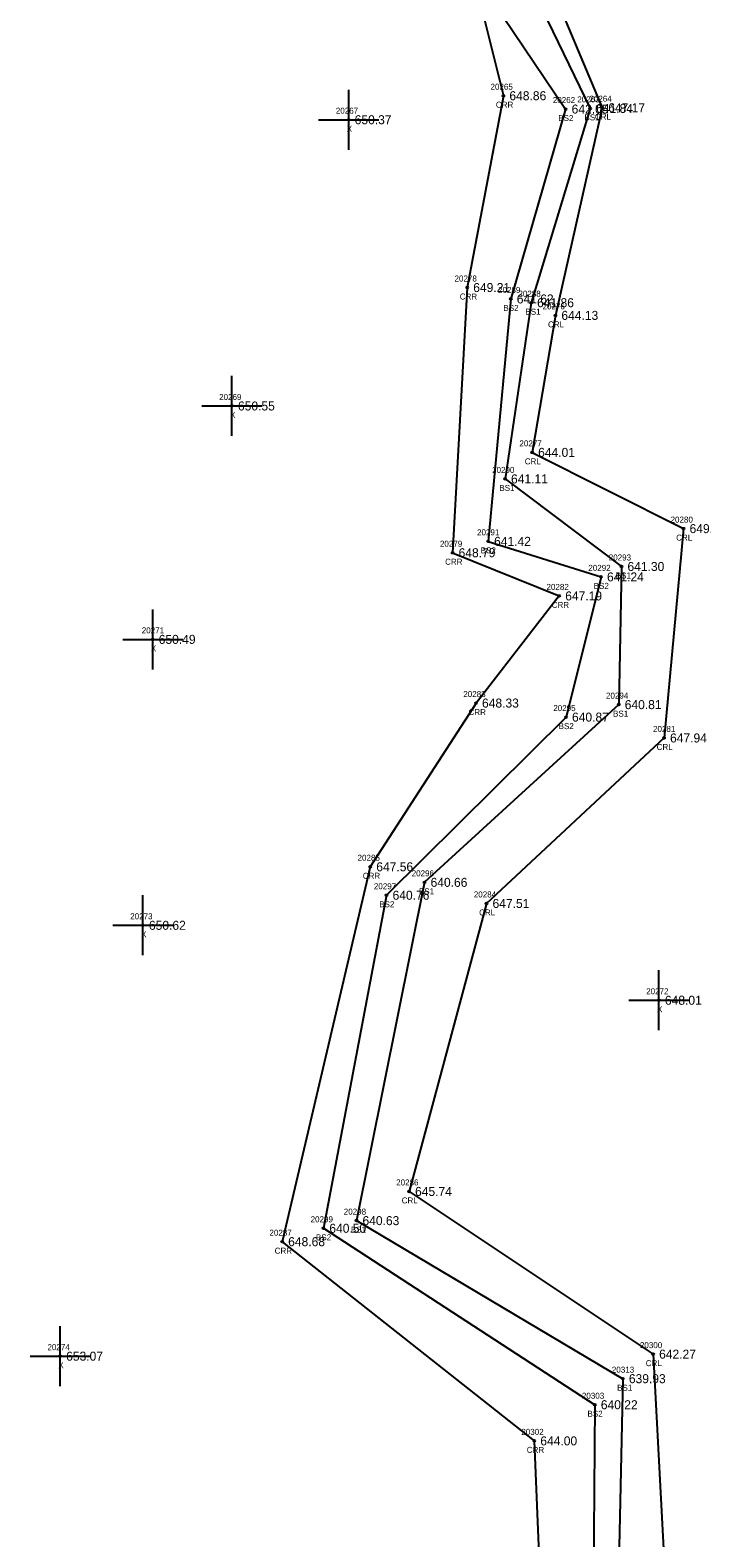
# Model space of a CAD drawing. Extents: x 1655675 to 1657082, y 1004080 to 1005193.
# Drawn here: x 1656286 to 1656397.9, y 1004331.4 to 1004582.5 of the extents above; entities that cross this region are included whole.
import ezdxf

# ---------------------------------------------------------------- set-up
doc = ezdxf.new("R2010")
doc.units = 0
for name, color, linetype in [('RD_DTM_BkLn2', 7, 'Continuous'), ('RD_DTM_BkLn_txCode', 7, 'Continuous'), ('RD_EX_H2O', 7, 'Continuous'), ('RD_EX_H2O_txCode', 7, 'Continuous'), ('RD_EX_Misc', 7, 'Continuous'), ('RD_EX_Misc_txCode', 7, 'Continuous'), ('RD_EX_TX_H2O_ELEV', 7, 'Continuous'), ('RD_EX_TX_Misc_ELEV', 7, 'Continuous'), ('RD_SMD_Locator', 7, 'Continuous')]:
    doc.layers.add(name, color=color, linetype=linetype)

msp = doc.modelspace()

# ---------------------------------------------------------------- linework, layer by layer
at = {"layer": 'RD_DTM_BkLn2'}
for points in [[(1656378.15, 1004634.61), (1656371.15, 1004611.72), (1656366.08, 1004597.97), (1656363.03, 1004587.4), (1656375.22, 1004569.39), (1656366.08, 1004537.76), (1656362.3, 1004497.38), (1656381.11, 1004491.46), (1656375.28, 1004468.1), (1656345.39, 1004438.43), (1656334.86, 1004382.95), (1656380.08, 1004353.56), (1656379.77, 1004310.89), (1656346.07, 1004296.22), (1656331.34, 1004265.79), (1656330.54, 1004261.76), (1656332.75, 1004222.72), (1656330.41, 1004184.19), (1656317.27, 1004148.27), (1656308.63, 1004093.1)], [(1656390.72, 1004627.52), (1656381.93, 1004608.13), (1656373.56, 1004597.19), (1656367.78, 1004593.37), (1656379.3, 1004569.5), (1656369.46, 1004537.13), (1656365.12, 1004507.78), (1656384.52, 1004493.19), (1656384.06, 1004470.18), (1656351.72, 1004440.58), (1656340.38, 1004384.23), (1656384.75, 1004357.9), (1656383.63, 1004306.92), (1656350.12, 1004294.84), (1656336.08, 1004262.67), (1656335.68, 1004261.32), (1656338.78, 1004223.26), (1656335.92, 1004183.08), (1656323.69, 1004146.56), (1656313.62, 1004092.92)]]:
    msp.add_lwpolyline(points, dxfattribs=at)
at = {"layer": 'RD_EX_H2O'}
for points in [[(1656368.16, 1004641.29), (1656361.32, 1004615.92), (1656361.94, 1004600.44), (1656360.19, 1004590.3), (1656364.85, 1004571.61), (1656358.83, 1004539.66), (1656356.39, 1004495.48), (1656374.15, 1004488.29), (1656360.29, 1004470.44), (1656342.68, 1004443.17), (1656328, 1004380.72), (1656370, 1004347.54), (1656371.38, 1004313.92), (1656341.06, 1004297.9), (1656327.33, 1004287.25), (1656316.16, 1004265.33), (1656323.68, 1004217.95), (1656315.99, 1004185.06), (1656305.45, 1004150.63), (1656296.74, 1004101.67)], [(1656396.09, 1004633.07), (1656388.01, 1004605.83), (1656383, 1004600.69), (1656372.14, 1004591.42), (1656381.32, 1004569.61), (1656373.51, 1004535.02), (1656369.64, 1004512.2), (1656394.86, 1004499.5), (1656391.61, 1004464.63), (1656362.04, 1004437.06), (1656349.14, 1004389.09), (1656389.79, 1004361.99), (1656392.68, 1004307.58), (1656360.76, 1004281.14), (1656349.55, 1004259.28), (1656348.46, 1004221.09), (1656343.48, 1004177.61), (1656328.72, 1004142.77), (1656319.4, 1004085.87)]]:
    msp.add_lwpolyline(points, dxfattribs=at)
at = {"layer": 'RD_EX_Misc'}
for p, q in [((1656339.08, 1004562.61), (1656339.08, 1004572.61)), ((1656334.08, 1004567.61), (1656344.08, 1004567.61)), ((1656319.64, 1004514.93), (1656319.64, 1004524.93)), ((1656314.64, 1004519.93), (1656324.64, 1004519.93)), ((1656306.44, 1004476.05), (1656306.44, 1004486.05)), ((1656301.44, 1004481.05), (1656311.44, 1004481.05)), ((1656304.81, 1004428.42), (1656304.81, 1004438.42)), ((1656299.81, 1004433.42), (1656309.81, 1004433.42)), ((1656390.76, 1004415.94), (1656390.76, 1004425.94)), ((1656385.76, 1004420.94), (1656395.76, 1004420.94)), ((1656291.02, 1004356.65), (1656291.02, 1004366.65)), ((1656286.02, 1004361.65), (1656296.02, 1004361.65))]:
    msp.add_line(p, q, dxfattribs=at)
at = {"layer": 'RD_SMD_Locator'}
for centre in [(1656364.85, 1004571.61), (1656375.22, 1004569.39), (1656379.3, 1004569.5), (1656381.32, 1004569.61), (1656339.08, 1004567.61), (1656358.83, 1004539.66), (1656366.08, 1004537.76), (1656369.46, 1004537.13), (1656373.51, 1004535.02), (1656319.64, 1004519.93), (1656369.64, 1004512.2), (1656365.12, 1004507.78), (1656394.86, 1004499.5), (1656356.39, 1004495.48), (1656362.3, 1004497.38), (1656384.52, 1004493.19), (1656381.11, 1004491.46), (1656374.15, 1004488.29), (1656306.44, 1004481.05), (1656360.29, 1004470.44), (1656384.06, 1004470.18), (1656375.28, 1004468.1), (1656391.61, 1004464.63), (1656342.68, 1004443.17), (1656351.72, 1004440.58), (1656345.39, 1004438.43), (1656362.04, 1004437.06), (1656304.81, 1004433.42), (1656390.76, 1004420.94), (1656349.14, 1004389.09), (1656334.86, 1004382.95), (1656340.38, 1004384.23), (1656328, 1004380.72), (1656389.79, 1004361.99), (1656291.02, 1004361.65), (1656384.75, 1004357.9), (1656380.08, 1004353.56), (1656370, 1004347.54)]:
    msp.add_circle(centre, 0.15, dxfattribs=at)

# ---------------------------------------------------------------- texts
at = {"layer": 'RD_DTM_BkLn_txCode'}
for s, p in [('20262', (1656373.08, 1004570.39)), ('20263', (1656377.16, 1004570.5)), ('BS2', (1656373.99, 1004567.39)), ('BS1', (1656378.36, 1004567.5)), ('20289', (1656363.96, 1004538.76)), ('20288', (1656367.35, 1004538.13)), ('BS2', (1656364.85, 1004535.76)), ('BS1', (1656368.52, 1004535.13)), ('20290', (1656362.97, 1004508.78)), ('BS1', (1656364.18, 1004505.78)), ('20291', (1656360.46, 1004498.38)), ('BS2', (1656361.07, 1004495.38)), ('20293', (1656382.4, 1004494.19)), ('20292', (1656379, 1004492.46)), ('BS2', (1656379.89, 1004489.46)), ('BS1', (1656383.57, 1004491.19)), ('20295', (1656373.16, 1004469.1)), ('20294', (1656381.94, 1004471.18)), ('BS1', (1656383.12, 1004468.18)), ('BS2', (1656374.05, 1004466.1)), ('20296', (1656349.57, 1004441.58)), ('20297', (1656343.27, 1004439.43)), ('BS2', (1656344.16, 1004436.43)), ('BS1', (1656350.77, 1004438.58)), ('20299', (1656332.74, 1004383.95)), ('20298', (1656338.26, 1004385.23)), ('BS1', (1656339.44, 1004382.23)), ('BS2', (1656333.63, 1004380.95)), ('20313', (1656382.92, 1004358.9)), ('20303', (1656377.93, 1004354.56)), ('BS1', (1656383.8, 1004355.9)), ('BS2', (1656378.86, 1004351.56))]:
    msp.add_text(s, height=1, dxfattribs=at).set_placement(p)
at = {"layer": 'RD_EX_H2O_txCode'}
for s, p in [('20265', (1656362.71, 1004572.61)), ('CRR', (1656363.6, 1004569.61)), ('20264', (1656379.18, 1004570.61)), ('CRL', (1656380.09, 1004567.61)), ('20278', (1656356.71, 1004540.66)), ('CRR', (1656357.58, 1004537.66)), ('20276', (1656371.37, 1004536.02)), ('CRL', (1656372.28, 1004533.02)), ('20277', (1656367.52, 1004513.2)), ('CRL', (1656368.41, 1004510.2)), ('20280', (1656392.7, 1004500.5)), ('CRL', (1656393.63, 1004497.5)), ('20279', (1656354.28, 1004496.48)), ('CRR', (1656355.14, 1004493.48)), ('20282', (1656372.03, 1004489.29)), ('CRR', (1656372.9, 1004486.29)), ('20283', (1656358.17, 1004471.44)), ('CRR', (1656359.04, 1004468.44)), ('20281', (1656389.77, 1004465.63)), ('CRL', (1656390.38, 1004462.63)), ('20285', (1656340.56, 1004444.17)), ('CRR', (1656341.43, 1004441.17)), ('20284', (1656359.92, 1004438.06)), ('CRL', (1656360.81, 1004435.06)), ('20286', (1656346.99, 1004390.09)), ('CRL', (1656347.91, 1004387.09)), ('20287', (1656325.88, 1004381.72)), ('CRR', (1656326.75, 1004378.72)), ('20300', (1656387.59, 1004362.99)), ('CRL', (1656388.56, 1004359.99)), ('20302', (1656367.84, 1004348.54)), ('CRR', (1656368.75, 1004345.54))]:
    msp.add_text(s, height=1, dxfattribs=at).set_placement(p)
at = {"layer": 'RD_EX_Misc_txCode'}
for s, p in [('20267', (1656336.94, 1004568.61)), ('X', (1656338.76, 1004565.61)), ('20269', (1656317.5, 1004520.93)), ('X', (1656319.33, 1004517.93)), ('20271', (1656304.61, 1004482.05)), ('X', (1656306.13, 1004479.05)), ('20273', (1656302.69, 1004434.42)), ('X', (1656304.5, 1004431.42)), ('20272', (1656388.64, 1004421.94)), ('X', (1656390.44, 1004418.94)), ('20274', (1656288.9, 1004362.65)), ('X', (1656290.71, 1004359.65))]:
    msp.add_text(s, height=1, dxfattribs=at).set_placement(p)
at = {"layer": 'RD_EX_TX_H2O_ELEV'}
for s, p in [('648.86', (1656365.85, 1004570.86)), ('647.17', (1656382.32, 1004568.86)), ('649.21', (1656359.83, 1004538.91)), ('644.13', (1656374.51, 1004534.27)), ('644.01', (1656370.64, 1004511.45)), ('649.07', (1656395.86, 1004498.75)), ('648.79', (1656357.39, 1004494.73)), ('647.19', (1656375.15, 1004487.54)), ('648.33', (1656361.29, 1004469.69)), ('647.94', (1656392.61, 1004463.88)), ('647.56', (1656343.68, 1004442.42)), ('647.51', (1656363.04, 1004436.31)), ('645.74', (1656350.14, 1004388.34)), ('648.68', (1656329, 1004379.97)), ('642.27', (1656390.79, 1004361.24)), ('644.00', (1656371, 1004346.79))]:
    msp.add_text(s, height=1.5, dxfattribs=at).set_placement(p)
at = {"layer": 'RD_EX_TX_Misc_ELEV'}
for s, p in [('650.37', (1656340.08, 1004566.86)), ('642.05', (1656376.22, 1004568.64)), ('641.84', (1656380.3, 1004568.75)), ('641.62', (1656367.08, 1004537.01)), ('641.86', (1656370.46, 1004536.38)), ('650.55', (1656320.64, 1004519.18)), ('641.11', (1656366.12, 1004507.03)), ('641.42', (1656363.3, 1004496.63)), ('641.30', (1656385.52, 1004492.44)), ('641.24', (1656382.11, 1004490.71)), ('650.49', (1656307.44, 1004480.3)), ('640.81', (1656385.06, 1004469.43)), ('640.87', (1656376.28, 1004467.35)), ('640.66', (1656352.72, 1004439.83)), ('640.76', (1656346.39, 1004437.68)), ('650.62', (1656305.81, 1004432.67)), ('648.01', (1656391.76, 1004420.19)), ('640.63', (1656341.38, 1004383.48)), ('640.50', (1656335.86, 1004382.2)), ('653.07', (1656292.02, 1004360.9)), ('639.93', (1656385.75, 1004357.15)), ('640.22', (1656381.08, 1004352.81))]:
    msp.add_text(s, height=1.5, dxfattribs=at).set_placement(p)

doc.saveas('drawing.dxf')
